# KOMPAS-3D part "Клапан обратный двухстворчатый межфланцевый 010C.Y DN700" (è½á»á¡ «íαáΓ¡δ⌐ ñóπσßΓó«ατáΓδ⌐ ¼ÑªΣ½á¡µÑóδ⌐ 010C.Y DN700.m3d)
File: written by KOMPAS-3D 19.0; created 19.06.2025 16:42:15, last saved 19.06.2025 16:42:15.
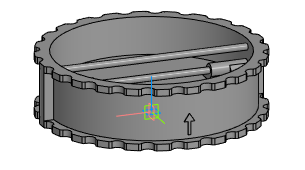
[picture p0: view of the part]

Document properties: Полное имя файла: E:\Dendor Работа Сачек\3D для проектировщиков\5.2 Тип 010C, 010C.Y Клапан обратный двухстворчатый межфланцевый\stp_Клапан обратный двухстворчатый межфланцевый 010C.Y\Клапан обратный двухстворчатый межфланцевый 010C.Y DN700.m3d

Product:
- Part/product: Клапан обратный двухстворчатый межфланцевый 010C.Y DN700

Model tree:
1. Операция без истории:1  (labels: Клапан обратный двухстворчатый межфланцевый 010C.Y DN700)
